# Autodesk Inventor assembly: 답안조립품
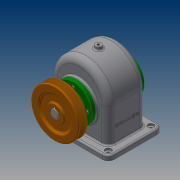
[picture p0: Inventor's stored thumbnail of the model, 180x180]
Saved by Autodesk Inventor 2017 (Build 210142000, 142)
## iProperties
Part Number: 답안조립품
Material: 일반
Document SubType Name: Assembly
Designer: 20
Author: 20
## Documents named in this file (13)
- C:\Users\20\Desktop\480310V1006\답안조립품.iam
- C:\Users\20\Desktop\480310V1006\본체.ipt
- C:\Users\20\Desktop\480310V1006\앞커버.ipt
- C:\Users\20\Desktop\480310V1006\뒤커버.ipt
- C:\Users\20\Desktop\480310V1006\베어링 6203.ipt
- C:\Users\20\Desktop\480310V1006\축.ipt
- C:\Users\20\Desktop\480310V1006\스퍼기어.ipt
- C:\Users\20\Desktop\480310V1006\키 6x6x22.ipt
- C:\Users\20\Desktop\480310V1006\부시.ipt
- C:\Users\20\Desktop\480310V1006\V-벨트풀리.ipt
- C:\Users\20\Desktop\480310V1006\멈춤나사 M4.ipt
- C:\Users\20\Desktop\480310V1006\키 5x5x18.ipt
- C:\Users\20\Desktop\480310V1006\볼트 M4.ipt
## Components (1 placed, 1 different names)
1. V-벨트풀리:1 — 플러쉬:2
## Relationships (1: Flush 1)
- 플러쉬:2 [Flush]: V-벨트풀리:1
